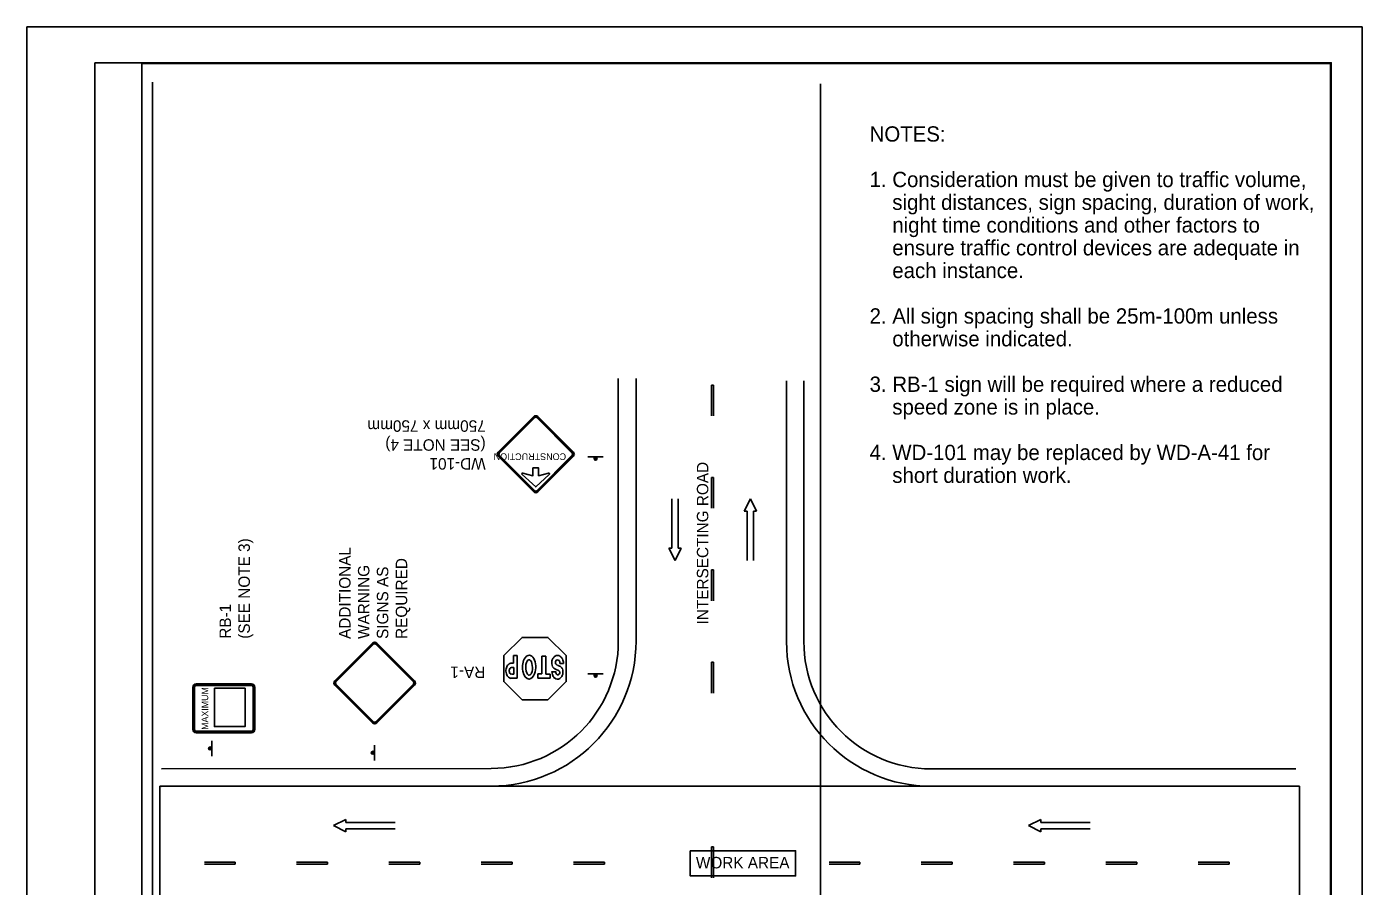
# Model space of a CAD drawing. Extents: x 1373 to 1583, y 130 to 399.
# Drawn here: x 1373.1 to 1583.1, y 263.9 to 399 of the extents above; entities that cross this region are included whole.
import ezdxf

# ---------------------------------------------------------------- set-up
doc = ezdxf.new("R2010")
doc.units = 0
for name, color, linetype in [('Level 1', 7, 'Continuous'), ('Level 10', 7, 'Continuous'), ('Level 17', 7, 'Continuous'), ('Level 18', 7, 'Continuous'), ('Level 2', 7, 'Continuous'), ('Level 60', 7, 'Continuous')]:
    doc.layers.add(name, color=color, linetype=linetype)

msp = doc.modelspace()

# ---------------------------------------------------------------- linework, layer by layer
at = {"layer": 'Level 10'}
for p, q in [((1392.81, 390.25), (1392.81, 138.3)), ((1497.88, 390.01), (1497.88, 138.3)), ((1466.08, 302.41), (1466.08, 343.67)), ((1468.86, 302.41), (1468.86, 343.67)), ((1492.53, 343.32), (1492.53, 302.34)), ((1495.25, 343.32), (1495.25, 302.34)), ((1474.51, 324.78), (1474.51, 317.04)), ((1475.48, 317.04), (1475.48, 324.78)), ((1485.87, 322.85), (1486.84, 324.79)), ((1486.84, 324.79), (1487.8, 322.85)), ((1486.35, 322.85), (1485.87, 322.85)), ((1486.35, 315.11), (1486.35, 322.85)), ((1487.8, 322.85), (1487.32, 322.85)), ((1487.32, 322.85), (1487.32, 315.11)), ((1474.03, 317.04), (1475, 315.11)), ((1474.51, 317.04), (1474.03, 317.04)), ((1475, 315.11), (1475.96, 317.04)), ((1475.96, 317.04), (1475.48, 317.04)), ((1449.58, 298.94), (1449.21, 298.94)), ((1449.22, 298.93), (1449.58, 298.94)), ((1449.65, 298.26), (1449.27, 298.26)), ((1449.65, 298.26), (1449.27, 298.26)), ((1449.58, 298.94), (1449.58, 300.17)), ((1449.58, 300.17), (1450.18, 300.17)), ((1449.65, 297.22), (1449.65, 298.26)), ((1449.65, 297.22), (1449.65, 298.26)), ((1450.18, 300.17), (1450.18, 296.57)), ((1454.06, 300.06), (1454.69, 300.06)), ((1454.06, 297.25), (1454.06, 300.06)), ((1454.69, 300.06), (1454.69, 297.24)), ((1457.46, 298.9), (1456.9, 298.9)), ((1457.28, 299.61), (1457.28, 299.61)), ((1450.18, 296.57), (1449.17, 296.57)), ((1449.26, 297.22), (1449.65, 297.22)), ((1449.26, 297.22), (1449.65, 297.22)), ((1452.09, 296.45), (1452.07, 296.45)), ((1452.11, 297.06), (1452.09, 297.05)), ((1453.44, 296.61), (1453.44, 297.25)), ((1453.44, 297.25), (1454.06, 297.25)), ((1455.35, 296.61), (1453.44, 296.61)), ((1454.69, 297.24), (1455.35, 297.24)), ((1455.35, 297.24), (1455.35, 296.61)), ((1455.64, 297.61), (1456.25, 297.61)), ((1394.25, 282.34), (1446.1, 282.41)), ((1515.25, 282.34), (1572.59, 282.34)), ((1394.25, 279.56), (1446.11, 279.63)), ((1515.25, 279.61), (1572.59, 279.61)), ((1423.23, 274.38), (1421.29, 273.42)), ((1421.29, 273.42), (1423.23, 272.45)), ((1423.23, 273.9), (1423.23, 274.38)), ((1430.97, 273.9), (1423.23, 273.9)), ((1532.52, 274.38), (1530.59, 273.42)), ((1530.59, 273.42), (1532.52, 272.45)), ((1532.52, 273.9), (1532.52, 274.38)), ((1540.26, 273.9), (1532.52, 273.9)), ((1423.23, 272.45), (1423.23, 272.93)), ((1423.23, 272.93), (1430.97, 272.93)), ((1532.52, 272.45), (1532.52, 272.93)), ((1532.52, 272.93), (1540.26, 272.93))]:
    msp.add_line(p, q, dxfattribs=at)
for points in [[(1448.07, 300.14), (1450.94, 303.01), (1455.02, 303.01), (1457.88, 300.14), (1457.88, 296.06), (1455.02, 293.19), (1450.94, 293.19), (1448.07, 296.06)], [(1573.19, 279.61), (1573.19, 256.04), (1394.01, 256.04), (1394.01, 279.61)], [(1477.39, 269.48), (1493.95, 269.48), (1493.95, 265.51), (1477.39, 265.51)]]:
    msp.add_lwpolyline(points, close=True, dxfattribs=at)
for centre, radius, start, end in [((1446.08, 302.41), 20, 270.0814, 0), ((1446.08, 302.41), 22.78, 270.0814, 0), ((1515.25, 302.34), 22.73, 180, 270), ((1515.25, 302.34), 20, 180, 270), ((1450.38, 297.65), 1.98, 158.3153, 168.6699), ((1449.44, 298.03), 0.968, 138.2922, 158.6031), ((1449.44, 298.03), 0.968, 138.2922, 158.6031), ((1449.19, 298.3), 0.597, 115.3838, 142.6188), ((1449.37, 298.08), 0.882, 106.602, 119.8091), ((1449.35, 297.87), 0.406, 101.9191, 145.7868), ((1449.35, 297.87), 0.406, 101.9191, 145.7868), ((1449.19, 298.73), 0.207, 79.7909, 113.5419), ((1457.77, 298.99), 2.16, 171.247, 183.9864), ((1457.14, 298.99), 1.53, 185.9097, 201.9865), ((1457.27, 298.84), 1.7, 145.5092, 163.2894), ((1453.87, 296.63), 2.57, 39.479, 43.426), ((1456.87, 299.32), 1.47, 226.2465, 247.9263), ((1456.67, 299.24), 0.977, 113.1413, 144.9906), ((1456.71, 299.07), 0.516, 146.253, 178.7323), ((1456.59, 299.02), 0.399, 172.5761, 210.4776), ((1456.6, 299.07), 0.435, 214.2083, 254.1552), ((1456.54, 299.07), 0.388, 95.4374, 134.0626), ((1456.52, 299.57), 0.612, 52.0536, 112.7397), ((1454, 292.21), 6.9, 64.4624, 68.8312), ((1456.51, 299.03), 0.419, 50.6966, 91.4573), ((1456.45, 299.07), 0.43, 6.8728, 42.7449), ((1456.05, 298.91), 0.856, 359.0172, 13.5172), ((1456.11, 298.97), 1.34, 28.4154, 53.6553), ((1456.44, 297.65), 0.952, 20.4481, 55.1107), ((1455.58, 298.82), 1.88, 2.3841, 24.9519), ((1449.93, 297.77), 1.52, 169.7521, 182.7916), ((1449.93, 297.77), 1.52, 169.7521, 182.7916), ((1450.3, 297.8), 1.89, 183.3903, 195.6597), ((1449.43, 297.52), 0.972, 193.0674, 213.762), ((1449.41, 297.43), 0.915, 209.2241, 228.5308), ((1449.41, 297.43), 0.915, 209.2241, 228.5308), ((1449.23, 297.16), 0.596, 224.8528, 265.0441), ((1449.51, 297.74), 0.585, 170.3417, 195.2342), ((1449.51, 297.74), 0.585, 170.3417, 195.2342), ((1449.45, 297.81), 0.522, 146.5086, 177.0313), ((1449.45, 297.81), 0.522, 146.5086, 177.0313), ((1449.49, 297.66), 0.55, 188.6031, 214.217), ((1449.49, 297.66), 0.55, 188.6031, 214.217), ((1449.32, 297.56), 0.354, 215.1198, 259.3117), ((1449.32, 297.56), 0.354, 215.1198, 259.3117), ((1457.2, 297.64), 1.55, 180.6952, 197.1452), ((1456.8, 297.46), 1.12, 194.564, 229.0063), ((1456.52, 297.1), 0.665, 226.1369, 301.3987), ((1456.74, 297.54), 0.506, 170.4412, 219.3244), ((1455.64, 295.97), 2.1, 57.9816, 70.979), ((1456.58, 297.47), 0.346, 227.3017, 289.0119), ((1456.55, 297.45), 0.331, 293.8064, 352.2407), ((1456.59, 297.5), 0.302, 344.131, 58.1476), ((1456.27, 297.44), 1.09, 303.3662, 335.6734), ((1455.85, 297.57), 1.52, 337.7332, 357.1392), ((1456.04, 297.61), 1.34, 354.8171, 15.9183)]:
    msp.add_arc(centre, radius, start, end, dxfattribs=at)
for centre, major_axis, ratio, start_param, end_param in [((1452.05, 298.32), (0.01, 1.87), 0.558644, 4.129576, 6.939747), ((1452.05, 298.32), (0.01, 1.87), 0.558644, 0.656861, 3.168126), ((1452.05, 298.27), (-0.01, 1.22), 0.432619, 0.881967, 3.190734), ((1452.05, 298.27), (-0.01, 1.22), 0.432619, 3.890436, 7.165085), ((1452.05, 298.32), (0.01, 1.87), 0.558644, 3.185857, 4.129398), ((1452.05, 298.27), (-0.01, 1.22), 0.432619, 3.239639, 3.888884)]:
    msp.add_ellipse(centre, major_axis=major_axis, ratio=ratio, start_param=start_param, end_param=end_param, dxfattribs=at)
at = {"layer": 'Level 17'}
for p, q in [((1383.77, 393.31), (1383.77, 393.31)), ((1447.18, 332.11), (1452.78, 337.7)), ((1447.26, 332.02), (1452.86, 337.62)), ((1447.34, 331.94), (1452.94, 337.54)), ((1453.24, 337.54), (1458.84, 331.94)), ((1453.33, 337.62), (1458.92, 332.02)), ((1453.41, 337.7), (1459.01, 332.11)), ((1452.78, 325.87), (1447.18, 331.47)), ((1452.86, 325.95), (1447.26, 331.56)), ((1452.94, 326.04), (1447.34, 331.64)), ((1458.84, 331.64), (1453.24, 326.04)), ((1458.92, 331.56), (1453.33, 325.95)), ((1459.01, 331.47), (1453.41, 325.87)), ((1459.32, 331.79), (1459.32, 331.79)), ((1463.71, 331.37), (1461.29, 331.37)), ((1455.11, 328.81), (1455.11, 328.81)), ((1455.11, 328.81), (1455.11, 328.81)), ((1455.11, 328.81), (1455.11, 328.81)), ((1421.49, 296.19), (1427.42, 302.11)), ((1421.58, 296.1), (1427.51, 302.02)), ((1421.67, 296.01), (1427.59, 301.93)), ((1427.94, 301.93), (1433.87, 296.01)), ((1428.03, 302.02), (1433.96, 296.1)), ((1428.12, 302.11), (1434.05, 296.19)), ((1421.49, 296.18), (1421.49, 296.19)), ((1463.71, 297.27), (1461.29, 297.27)), ((1399.19, 288.51), (1399.19, 295.19)), ((1399.32, 288.51), (1399.32, 295.19)), ((1399.45, 288.51), (1399.45, 295.19)), ((1399.7, 295.7), (1408.4, 295.7)), ((1399.7, 295.57), (1408.4, 295.57)), ((1399.7, 295.44), (1408.4, 295.44)), ((1408.66, 295.19), (1408.66, 288.51)), ((1408.79, 295.19), (1408.79, 288.51)), ((1408.91, 295.19), (1408.91, 288.51)), ((1427.42, 289.55), (1421.49, 295.49)), ((1421.58, 296.1), (1421.58, 296.1)), ((1427.51, 289.64), (1421.58, 295.57)), ((1421.67, 296.01), (1421.67, 296.01)), ((1427.59, 289.73), (1421.67, 295.66)), ((1433.87, 295.66), (1427.94, 289.73)), ((1433.96, 295.57), (1428.03, 289.64)), ((1434.05, 295.49), (1428.12, 289.55)), ((1399.19, 288.51), (1399.19, 288.51)), ((1399.24, 288.39), (1399.24, 288.4)), ((1399.29, 288.28), (1399.29, 288.28)), ((1408.4, 288.26), (1399.7, 288.26)), ((1408.4, 288.13), (1399.7, 288.13)), ((1408.4, 288), (1399.7, 288)), ((1402.16, 284.34), (1402.16, 286.76)), ((1427.74, 283.66), (1427.74, 286.08))]:
    msp.add_line(p, q, dxfattribs=at)
for points in [[(1455.23, 328.58), (1453.09, 326.64), (1450.95, 328.58)], [(1455.23, 328.58), (1453.09, 326.64), (1450.95, 328.58)], [(1455.23, 328.58), (1453.09, 326.64), (1450.95, 328.58)], [(1451.08, 328.81), (1452.65, 328.41), (1452.65, 329.63), (1453.54, 329.63), (1453.54, 328.41), (1455.11, 328.81)], [(1451.08, 328.81), (1452.65, 328.41), (1452.65, 329.63), (1453.54, 329.63), (1453.54, 328.41), (1455.11, 328.81)], [(1451.08, 328.81), (1452.65, 328.41), (1452.65, 329.63), (1453.54, 329.63), (1453.54, 328.41), (1455.11, 328.81)]]:
    msp.add_lwpolyline(points, dxfattribs=at)
msp.add_lwpolyline([(1402.58, 295), (1407.39, 295), (1407.39, 288.99), (1402.58, 288.99)], close=True, dxfattribs=at)
for centre, radius in [((1462.5, 331.1), 0.242), ((1462.5, 331.1), 0.121), ((1462.5, 297), 0.242), ((1462.5, 297), 0.121), ((1401.89, 285.55), 0.242), ((1401.89, 285.55), 0.121), ((1427.47, 284.87), 0.242), ((1427.47, 284.87), 0.121)]:
    msp.add_circle(centre, radius, dxfattribs=at)
for centre, radius, start, end in [((1453.09, 337.39), 0.447, 45, 135), ((1453.09, 337.39), 0.329, 45, 135), ((1453.09, 337.39), 0.212, 45, 135), ((1447.49, 331.79), 0.447, 135, 225), ((1447.49, 331.79), 0.329, 135, 225), ((1447.49, 331.79), 0.212, 135, 225), ((1458.69, 331.79), 0.212, 315, 45), ((1458.69, 331.79), 0.329, 315, 45), ((1458.69, 331.79), 0.447, 315, 45), ((1451.04, 328.68), 0.134, 75.5925, 227.6952), ((1451.04, 328.68), 0.134, 75.5925, 227.6952), ((1451.04, 328.68), 0.134, 75.5925, 227.6952), ((1455.14, 328.68), 0.134, 312.3048, 104.4075), ((1455.14, 328.68), 0.134, 312.3048, 104.4075), ((1455.14, 328.68), 0.134, 312.3048, 104.4075), ((1453.09, 326.19), 0.447, 225, 315), ((1453.09, 326.19), 0.329, 225, 315), ((1453.09, 326.19), 0.212, 225, 315), ((1427.77, 301.76), 0.496, 45, 135), ((1427.77, 301.76), 0.371, 45, 135), ((1427.77, 301.76), 0.246, 45, 135), ((1421.84, 295.83), 0.496, 135, 225), ((1433.69, 295.83), 0.496, 315, 45), ((1399.7, 295.18), 0.515, 90, 180), ((1399.7, 295.18), 0.386, 90, 180), ((1399.7, 295.18), 0.258, 90, 180), ((1408.4, 295.18), 0.515, 0, 90), ((1408.4, 295.18), 0.386, 0, 90), ((1408.4, 295.18), 0.258, 0, 90), ((1421.84, 295.83), 0.371, 135, 225), ((1421.84, 295.83), 0.246, 135, 225), ((1433.69, 295.83), 0.246, 315, 45), ((1433.69, 295.83), 0.371, 315, 45), ((1399.7, 288.51), 0.515, 180, 270), ((1399.7, 288.51), 0.386, 180, 270), ((1399.7, 288.51), 0.258, 180, 270), ((1408.4, 288.51), 0.515, 270, 0), ((1408.4, 288.51), 0.386, 270, 0), ((1408.4, 288.51), 0.258, 270, 0), ((1427.77, 289.91), 0.496, 225, 315), ((1427.77, 289.91), 0.371, 225, 315), ((1427.77, 289.91), 0.246, 225, 315)]:
    msp.add_arc(centre, radius, start, end, dxfattribs=at)
at = {"layer": 'Level 2'}
for p, q in [((1480.75, 342.64), (1480.75, 337.8)), ((1481.04, 342.64), (1480.75, 342.64)), ((1481.04, 337.8), (1481.04, 342.64)), ((1480.75, 328.12), (1480.75, 323.29)), ((1481.04, 328.12), (1480.75, 328.12)), ((1481.04, 323.29), (1481.04, 328.12)), ((1480.75, 313.61), (1480.75, 308.77)), ((1481.04, 313.61), (1480.75, 313.61)), ((1481.04, 308.77), (1481.04, 313.61)), ((1480.75, 299.1), (1480.75, 294.26)), ((1481.04, 299.1), (1480.75, 299.1)), ((1481.04, 294.26), (1481.04, 299.1)), ((1480.75, 270.07), (1480.75, 265.23)), ((1481.04, 270.07), (1480.75, 270.07)), ((1481.04, 265.23), (1481.04, 270.07)), ((1405.83, 267.66), (1400.99, 267.66)), ((1400.99, 267.37), (1405.83, 267.37)), ((1405.83, 267.37), (1405.83, 267.66)), ((1420.34, 267.66), (1415.5, 267.66)), ((1415.5, 267.37), (1420.34, 267.37)), ((1420.34, 267.37), (1420.34, 267.66)), ((1434.85, 267.66), (1430.02, 267.66)), ((1430.02, 267.37), (1434.85, 267.37)), ((1434.85, 267.37), (1434.85, 267.66)), ((1449.37, 267.66), (1444.53, 267.66)), ((1444.53, 267.37), (1449.37, 267.37)), ((1449.37, 267.37), (1449.37, 267.66)), ((1463.88, 267.66), (1459.04, 267.66)), ((1459.04, 267.37), (1463.88, 267.37)), ((1463.88, 267.37), (1463.88, 267.66)), ((1504.05, 267.66), (1499.21, 267.66)), ((1499.21, 267.37), (1504.05, 267.37)), ((1504.05, 267.37), (1504.05, 267.66)), ((1518.56, 267.66), (1513.72, 267.66)), ((1513.72, 267.37), (1518.56, 267.37)), ((1518.56, 267.37), (1518.56, 267.66)), ((1533.07, 267.66), (1528.24, 267.66)), ((1528.24, 267.37), (1533.07, 267.37)), ((1533.07, 267.37), (1533.07, 267.66)), ((1547.59, 267.66), (1542.75, 267.66)), ((1542.75, 267.37), (1547.59, 267.37)), ((1547.59, 267.37), (1547.59, 267.66)), ((1562.1, 267.66), (1557.26, 267.66)), ((1557.26, 267.37), (1562.1, 267.37)), ((1562.1, 267.37), (1562.1, 267.66))]:
    msp.add_line(p, q, dxfattribs=at)
at = {"layer": 'Level 60'}
for p, q in [((1583.06, 398.98), (1373.06, 398.98)), ((1373.06, 398.98), (1373.06, 129.98)), ((1583.06, 129.98), (1583.06, 398.98))]:
    msp.add_line(p, q, dxfattribs=at)
for points in [[(1383.77, 393.31), (1578.17, 393.31), (1578.17, 135.56), (1383.77, 135.56)], [(1391.18, 393.17), (1578.06, 393.17), (1578.06, 135.79), (1391.18, 135.79)]]:
    msp.add_lwpolyline(points, close=True, dxfattribs=at)

# ---------------------------------------------------------------- texts
at = {"layer": 'Level 1'}
for s, p in [('NOTES:', (1505.59, 380.92)), ('1. Consideration must be given to traffic volume,', (1505.59, 373.77)), ('    sight distances, sign spacing, duration of work,', (1505.59, 370.19)), ('    night time conditions and other factors to ', (1505.59, 366.62)), ('    ensure traffic control devices are adequate in ', (1505.59, 363.04)), ('    each instance.', (1505.59, 359.47)), ('2. All sign spacing shall be 25m-100m unless', (1505.59, 352.32)), ('    otherwise indicated.', (1505.59, 348.74)), ('3. RB-1 sign will be required where a reduced ', (1505.59, 341.59)), ('    speed zone is in place.', (1505.59, 338.02)), ('4. WD-101 may be replaced by WD-A-41 for ', (1505.59, 330.87)), ('    short duration work.', (1505.59, 327.29))]:
    msp.add_text(s, height=2.4, dxfattribs=at).set_placement(p)
at = {"layer": 'Level 10'}
for s, rotation, p in [('INTERSECTING ROAD', 90, (1480.23, 305.04)), ('WORK AREA', 360, (1478.28, 266.7))]:
    msp.add_text(s, height=1.8, rotation=rotation, dxfattribs=at).set_placement(p)
at = {"layer": 'Level 17'}
for s, height, rotation, p in [('750mm x 750mm', 1.8, 180, (1445.22, 337.12)), ('(SEE NOTE 4)', 1.8, 180, (1445.22, 334.14)), ('CONSTRUCTION', 1.0575, 180, (1457.87, 331.93)), ('WD-101', 1.8, 180, (1445.22, 331.17)), ('ADDITIONAL ', 1.7999, 90, (1423.97, 302.76)), ('REQUIRED', 1.8, 90, (1432.88, 302.76)), ('WARNING ', 1.8, 90, (1426.94, 302.76)), ('SIGNS AS ', 1.8, 90, (1429.91, 302.76)), ('RA-1', 1.8, 180, (1445.16, 298.42)), ('MAXIMUM', 1.039, 90, (1401.59, 288.47))]:
    msp.add_text(s, height=height, rotation=rotation, dxfattribs=at).set_placement(p)
at = {"layer": 'Level 18'}
for s, p in [('(SEE NOTE 3)', (1408.15, 302.79)), ('RB-1', (1405.17, 302.79))]:
    msp.add_text(s, height=1.8, rotation=90, dxfattribs=at).set_placement(p)

doc.saveas('drawing.dxf')
